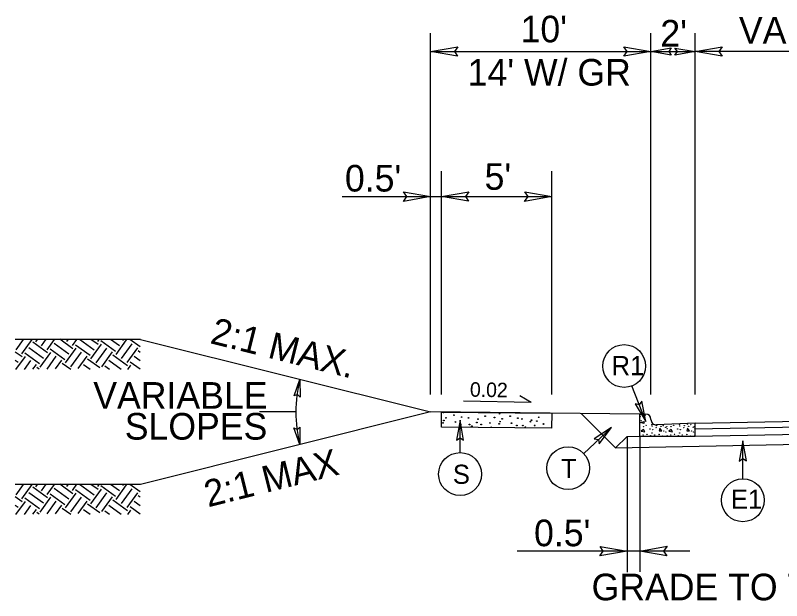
# Model space of a CAD drawing. Extents: x 3025871 to 3026431, y 707165 to 707825.
# Drawn here: x 3026298.56 to 3026333.34, y 707641.03 to 707667.61 of the extents above; entities that cross this region are included whole.
import ezdxf

# ---------------------------------------------------------------- set-up
doc = ezdxf.new("R2010")
doc.units = 0
for name, color, linetype in [('Prop Drainage Structure Junction Box with Manhole CELL', 7, 'Continuous'), ('Prop Drainage Structure Junction Box with Slab Lid TB 840 34 CELL', 7, 'Continuous'), ('Prop Drainage Structure Plot Symbol 50 Scale', 7, 'Continuous'), ('Prop Pavement Schedule Description CELL', 7, 'Continuous'), ('Sheet Plot Border Inside CELL', 7, 'Continuous'), ('Sheet Sticker Incomplete CELL', 7, 'Continuous'), ('Sheet Typical CELL', 7, 'Continuous'), ('Typical Arrow Superelevation CELL', 7, 'Continuous'), ('Typical Grade Point Symbol CELL', 7, 'Continuous'), ('Typical Text Centerline CELL', 7, 'Continuous'), ('Typical Text Grade Point CELL', 7, 'Continuous')]:
    doc.layers.add(name, color=color, linetype=linetype)

msp = doc.modelspace()

# ---------------------------------------------------------------- linework, layer by layer
at = {"layer": 'Prop Drainage Structure Junction Box with Manhole CELL'}
msp.add_line((3026325.802, 707647.974), (3026348.144, 707648.421), dxfattribs=at)
at = {"layer": 'Prop Drainage Structure Junction Box with Slab Lid TB 840 34 CELL'}
for p, q in [((3026317.406, 707650.399), (3026317.406, 707666.8)), ((3026327.406, 707650.399), (3026327.406, 707666.8)), ((3026329.412, 707650.658), (3026329.412, 707666.8)), ((3026317.406, 707665.967), (3026327.406, 707665.967)), ((3026327.406, 707665.967), (3026329.412, 707665.967)), ((3026350.162, 707665.967), (3026329.412, 707665.967)), ((3026329.412, 707650.399), (3026329.412, 707665.704)), ((3026317.906, 707650.399), (3026317.906, 707660.529)), ((3026322.906, 707650.399), (3026322.906, 707660.529)), ((3026313.391, 707659.381), (3026322.906, 707659.381)), ((3026311.291, 707649.599), (3026309.635, 707649.599)), ((3026326.319, 707648.49), (3026326.319, 707642.327)), ((3026326.904, 707648.502), (3026326.904, 707642.339)), ((3026329.174, 707643.282), (3026321.332, 707643.282))]:
    msp.add_line(p, q, dxfattribs=at)
msp.add_arc((3026317.406, 707649.599), 6.116, 165.9638, 194.0362, dxfattribs=at)
at = {"layer": 'Prop Drainage Structure Plot Symbol 50 Scale'}
for p, q in [((3026326.904, 707648.502), (3026326.904, 707649.506)), ((3026326.904, 707649.506), (3026327.165, 707649.506)), ((3026326.94, 707649.126), (3026327.095, 707649.171)), ((3026327.078, 707649.08), (3026326.94, 707649.126)), ((3026327.095, 707649.171), (3026327.078, 707649.08)), ((3026327.405, 707649.255), (3026327.405, 707649.265)), ((3026329.412, 707649.088), (3026327.656, 707649.015)), ((3026329.412, 707648.502), (3026329.412, 707649.088)), ((3026327.067, 707648.807), (3026326.963, 707648.731)), ((3026326.963, 707648.731), (3026327.129, 707648.692)), ((3026327.129, 707648.692), (3026327.067, 707648.807)), ((3026327.811, 707648.863), (3026327.777, 707648.749)), ((3026327.777, 707648.749), (3026327.897, 707648.743)), ((3026327.897, 707648.743), (3026327.811, 707648.863)), ((3026328.32, 707648.807), (3026328.217, 707648.731)), ((3026328.217, 707648.731), (3026328.383, 707648.692)), ((3026328.383, 707648.692), (3026328.32, 707648.807)), ((3026329.064, 707648.863), (3026329.03, 707648.749)), ((3026329.03, 707648.749), (3026329.151, 707648.743)), ((3026329.151, 707648.743), (3026329.064, 707648.863)), ((3026326.904, 707648.502), (3026329.412, 707648.502))]:
    msp.add_line(p, q, dxfattribs=at)
for centre in [(3026326.917, 707649.395), (3026327.135, 707649.43), (3026326.969, 707649.212), (3026327.187, 707648.989), (3026327.444, 707649.017), (3026327.668, 707648.983), (3026327.96, 707648.987), (3026328.44, 707648.989), (3026328.698, 707649.017), (3026328.921, 707648.983), (3026329.07, 707649.046), (3026329.214, 707649.029), (3026327.066, 707648.938), (3026327.364, 707648.823), (3026327.456, 707648.64), (3026327.461, 707648.967), (3026327.49, 707648.795), (3026327.639, 707648.881), (3026327.863, 707648.944), (3026327.988, 707648.743), (3026328.069, 707648.904), (3026328.085, 707648.697), (3026328.125, 707648.938), (3026328.142, 707648.841), (3026328.32, 707648.938), (3026328.618, 707648.823), (3026328.709, 707648.64), (3026328.715, 707648.967), (3026328.744, 707648.795), (3026328.893, 707648.881), (3026329.116, 707648.944), (3026329.242, 707648.743), (3026329.322, 707648.904), (3026329.339, 707648.697), (3026329.379, 707648.938), (3026329.396, 707648.841), (3026327.049, 707648.548), (3026327.221, 707648.589), (3026327.398, 707648.526), (3026327.57, 707648.554), (3026327.777, 707648.577), (3026327.937, 707648.508), (3026328.148, 707648.531), (3026328.303, 707648.548), (3026328.474, 707648.589), (3026328.652, 707648.526), (3026328.824, 707648.554), (3026329.03, 707648.577), (3026329.191, 707648.508), (3026329.402, 707648.531)]:
    msp.add_circle(centre, 0.00805, dxfattribs=at)
for centre, start, end in [((3026327.165, 707649.265), 0, 90), ((3026327.646, 707649.255), 180, 272.3845)]:
    msp.add_arc(centre, 0.24, start, end, dxfattribs=at)
at = {"layer": 'Prop Pavement Schedule Description CELL'}
for p, q in [((3026329.412, 707649.088), (3026362.162, 707649.743)), ((3026329.412, 707648.838), (3026348.148, 707649.212)), ((3026329.412, 707648.504), (3026348.146, 707648.879))]:
    msp.add_line(p, q, dxfattribs=at)
at = {"layer": 'Sheet Plot Border Inside CELL'}
msp.add_line((3026326.319, 707648.49), (3026326.904, 707648.502), dxfattribs=at)
at = {"layer": 'Sheet Sticker Incomplete CELL'}
for q in [(3026318.898, 707650.084), (3026321.45, 707650.338)]:
    msp.add_line((3026321.966, 707650.027), q, dxfattribs=at)
at = {"layer": 'Sheet Typical CELL'}
for p, q in [((3026326.904, 707649.506), (3026317.406, 707649.599)), ((3026317.893, 707648.917), (3026317.906, 707649.594)), ((3026317.906, 707649.594), (3026322.906, 707649.545)), ((3026322.906, 707649.545), (3026322.893, 707648.868)), ((3026325.802, 707647.974), (3026324.244, 707649.532)), ((3026322.893, 707648.868), (3026317.893, 707648.917)), ((3026326.319, 707648.49), (3026325.802, 707647.974))]:
    msp.add_line(p, q, dxfattribs=at)
for centre in [(3026317.989, 707649.572), (3026318.101, 707649.336), (3026318.465, 707649.458), (3026318.813, 707649.369), (3026319.127, 707649.328), (3026319.884, 707649.406), (3026320.302, 707649.351), (3026320.539, 707649.522), (3026321.015, 707649.408), (3026321.363, 707649.319), (3026322.31, 707649.359), (3026317.968, 707649.11), (3026318.005, 707649.213), (3026318.528, 707649.144), (3026318.771, 707649.036), (3026319.168, 707649.028), (3026319.505, 707649.121), (3026319.555, 707649.273), (3026319.702, 707649.029), (3026320.1, 707649.101), (3026320.518, 707649.06), (3026320.555, 707649.162), (3026320.651, 707649.286), (3026321.078, 707649.094), (3026321.321, 707648.986), (3026321.553, 707649.28), (3026321.594, 707648.981), (3026321.933, 707649.159), (3026321.981, 707649.225), (3026322.128, 707648.982), (3026322.225, 707649.188), (3026322.526, 707649.054), (3026319.28, 707648.956), (3026321.707, 707648.909)]:
    msp.add_circle(centre, 0.0164, dxfattribs=at)
msp.add_arc((3026320.154, 707648.892), 0.0164, 7.8354, 171.0404, dxfattribs=at)
at = {"layer": 'Typical Grade Point Symbol CELL'}
for p, q in [((3026327.167, 707649.173), (3026326.543, 707650.781)), ((3026318.742, 707647.753), (3026318.741, 707649.228)), ((3026324.355, 707647.709), (3026325.612, 707648.889)), ((3026331.579, 707646.562), (3026331.578, 707648.287))]:
    msp.add_line(p, q, dxfattribs=at)
for centre in [(3026326.192, 707651.687), (3026323.645, 707647.045), (3026318.742, 707646.781), (3026331.579, 707645.59)]:
    msp.add_circle(centre, 0.972, dxfattribs=at)
at = {"layer": 'Typical Text Centerline CELL'}
for points in [[(3026318.632, 707665.756), (3026317.406, 707665.967), (3026318.638, 707666.185), (3026318.482, 707665.967)], [(3026326.181, 707666.178), (3026327.406, 707665.967), (3026326.174, 707665.75), (3026326.331, 707665.967)], [(3026328.325, 707665.809), (3026327.406, 707665.967), (3026328.33, 707666.131), (3026328.212, 707665.967)], [(3026328.496, 707666.126), (3026329.414, 707665.967), (3026328.491, 707665.804), (3026328.608, 707665.967)], [(3026330.638, 707665.756), (3026329.412, 707665.967), (3026330.644, 707666.185), (3026330.488, 707665.967)], [(3026316.181, 707659.592), (3026317.406, 707659.381), (3026316.174, 707659.163), (3026316.331, 707659.381)], [(3026319.132, 707659.17), (3026317.906, 707659.381), (3026319.138, 707659.599), (3026318.982, 707659.381)], [(3026321.681, 707659.592), (3026322.906, 707659.381), (3026321.674, 707659.163), (3026321.831, 707659.381)], [(3026311.209, 707650.326), (3026311.474, 707651.082), (3026311.481, 707650.276), (3026311.359, 707650.398)], [(3026326.691, 707649.965), (3026327.167, 707649.173), (3026326.986, 707650.084), (3026326.878, 707649.918)], [(3026318.898, 707648.318), (3026318.741, 707649.227), (3026318.58, 707648.313), (3026318.741, 707648.429)], [(3026311.476, 707648.917), (3026311.474, 707648.116), (3026311.203, 707648.876), (3026311.358, 707648.8)], [(3026325.056, 707648.153), (3026325.612, 707648.889), (3026324.835, 707648.381), (3026325.03, 707648.343)], [(3026331.735, 707647.377), (3026331.578, 707648.287), (3026331.416, 707647.372), (3026331.578, 707647.488)], [(3026325.094, 707643.493), (3026326.319, 707643.282), (3026325.088, 707643.065), (3026325.244, 707643.282)], [(3026328.129, 707643.071), (3026326.904, 707643.282), (3026328.136, 707643.5), (3026327.979, 707643.282)]]:
    msp.add_lwpolyline(points, close=True, dxfattribs=at)
at = {"layer": 'Typical Text Grade Point CELL'}
for p, q in [((3026304.241, 707652.89), (3026298.557, 707652.89)), ((3026304.241, 707652.89), (3026298.557, 707652.89)), ((3026298.597, 707652.421), (3026298.935, 707652.89)), ((3026298.597, 707652.421), (3026298.935, 707652.89)), ((3026298.848, 707652.24), (3026299.315, 707652.89)), ((3026298.848, 707652.24), (3026299.315, 707652.89)), ((3026299.495, 707652.789), (3026299.568, 707652.89)), ((3026299.495, 707652.789), (3026299.568, 707652.89)), ((3026299.746, 707652.609), (3026299.957, 707652.902)), ((3026299.746, 707652.609), (3026299.957, 707652.902)), ((3026299.996, 707652.428), (3026300.328, 707652.89)), ((3026299.996, 707652.428), (3026300.328, 707652.89)), ((3026301.169, 707652.473), (3026300.574, 707652.901)), ((3026301.169, 707652.473), (3026300.574, 707652.901)), ((3026300.894, 707652.797), (3026300.968, 707652.899)), ((3026300.894, 707652.797), (3026300.968, 707652.899)), ((3026301.145, 707652.617), (3026301.348, 707652.898)), ((3026301.145, 707652.617), (3026301.348, 707652.898)), ((3026302.137, 707652.41), (3026301.469, 707652.891)), ((3026302.137, 707652.41), (3026301.469, 707652.891)), ((3026302.317, 707652.661), (3026301.99, 707652.896)), ((3026302.317, 707652.661), (3026301.99, 707652.896)), ((3026302.294, 707652.805), (3026302.359, 707652.895)), ((3026302.294, 707652.805), (3026302.359, 707652.895)), ((3026303.106, 707652.348), (3026302.437, 707652.828)), ((3026303.106, 707652.348), (3026302.437, 707652.828)), ((3026303.286, 707652.598), (3026302.875, 707652.894)), ((3026303.286, 707652.598), (3026302.875, 707652.894)), ((3026303.129, 707652.204), (3026303.61, 707652.873)), ((3026303.129, 707652.204), (3026303.61, 707652.873)), ((3026303.466, 707652.849), (3026303.406, 707652.892)), ((3026303.466, 707652.849), (3026303.406, 707652.892)), ((3026304.22, 707652.561), (3026303.76, 707652.891)), ((3026304.22, 707652.561), (3026303.76, 707652.891)), ((3026304.241, 707652.89), (3026317.406, 707649.599)), ((3026299.84, 707652.034), (3026299.171, 707652.515)), ((3026299.84, 707652.034), (3026299.171, 707652.515)), ((3026300.02, 707652.285), (3026299.352, 707652.765)), ((3026300.02, 707652.285), (3026299.352, 707652.765)), ((3026300.989, 707652.222), (3026300.32, 707652.703)), ((3026300.989, 707652.222), (3026300.32, 707652.703)), ((3026300.832, 707651.828), (3026301.312, 707652.496)), ((3026300.832, 707651.828), (3026301.312, 707652.496)), ((3026301.957, 707652.16), (3026301.289, 707652.64)), ((3026301.957, 707652.16), (3026301.289, 707652.64)), ((3026301.981, 707652.016), (3026302.461, 707652.685)), ((3026301.981, 707652.016), (3026302.461, 707652.685)), ((3026302.231, 707651.836), (3026302.712, 707652.504)), ((3026302.231, 707651.836), (3026302.712, 707652.504)), ((3026303.38, 707652.024), (3026303.86, 707652.692)), ((3026303.38, 707652.024), (3026303.86, 707652.692)), ((3026303.631, 707651.844), (3026304.111, 707652.512)), ((3026303.631, 707651.844), (3026304.111, 707652.512)), ((3026298.871, 707652.097), (3026298.557, 707652.323)), ((3026298.871, 707652.097), (3026298.557, 707652.323)), ((3026298.585, 707651.522), (3026299.015, 707652.12)), ((3026298.585, 707651.522), (3026299.015, 707652.12)), ((3026299.66, 707651.784), (3026298.991, 707652.264)), ((3026299.66, 707651.784), (3026298.991, 707652.264)), ((3026299.683, 707651.64), (3026300.164, 707652.308)), ((3026299.683, 707651.64), (3026300.164, 707652.308)), ((3026299.999, 707651.55), (3026300.414, 707652.128)), ((3026299.999, 707651.55), (3026300.414, 707652.128)), ((3026300.808, 707651.972), (3026300.14, 707652.452)), ((3026300.808, 707651.972), (3026300.14, 707652.452)), ((3026301.083, 707651.648), (3026301.563, 707652.316)), ((3026301.083, 707651.648), (3026301.563, 707652.316)), ((3026301.413, 707651.579), (3026301.814, 707652.136)), ((3026301.413, 707651.579), (3026301.814, 707652.136)), ((3026302.482, 707651.656), (3026302.962, 707652.324)), ((3026302.482, 707651.656), (3026302.962, 707652.324)), ((3026303.654, 707651.7), (3026302.986, 707652.181)), ((3026303.654, 707651.7), (3026302.986, 707652.181)), ((3026304.22, 707651.928), (3026303.954, 707652.118)), ((3026304.22, 707651.928), (3026303.954, 707652.118)), ((3026304.22, 707652.308), (3026304.134, 707652.369)), ((3026304.22, 707652.308), (3026304.134, 707652.369)), ((3026298.691, 707651.846), (3026298.557, 707651.943)), ((3026298.691, 707651.846), (3026298.557, 707651.943)), ((3026298.97, 707651.53), (3026299.265, 707651.94)), ((3026298.97, 707651.53), (3026299.265, 707651.94)), ((3026300.384, 707651.558), (3026300.665, 707651.948)), ((3026300.384, 707651.558), (3026300.665, 707651.948)), ((3026301.07, 707651.53), (3026300.688, 707651.805)), ((3026301.07, 707651.53), (3026300.688, 707651.805)), ((3026302.386, 707651.598), (3026301.837, 707651.993)), ((3026302.386, 707651.598), (3026301.837, 707651.993)), ((3026303.362, 707651.53), (3026302.806, 707651.93)), ((3026303.362, 707651.53), (3026302.806, 707651.93)), ((3026304.22, 707651.547), (3026303.774, 707651.867)), ((3026304.22, 707651.547), (3026303.774, 707651.867)), ((3026299.356, 707651.537), (3026299.516, 707651.76)), ((3026299.356, 707651.537), (3026299.516, 707651.76)), ((3026299.642, 707651.543), (3026299.54, 707651.616)), ((3026299.642, 707651.543), (3026299.54, 707651.616)), ((3026301.952, 707651.53), (3026301.657, 707651.742)), ((3026301.952, 707651.53), (3026301.657, 707651.742)), ((3026302.833, 707651.53), (3026302.626, 707651.679)), ((3026302.833, 707651.53), (3026302.626, 707651.679)), ((3026303.659, 707651.53), (3026303.798, 707651.724)), ((3026303.659, 707651.53), (3026303.798, 707651.724)), ((3026317.406, 707649.599), (3026304.241, 707646.308)), ((3026304.241, 707646.308), (3026298.557, 707646.308)), ((3026304.241, 707646.308), (3026298.557, 707646.308)), ((3026298.597, 707645.838), (3026298.935, 707646.308)), ((3026298.597, 707645.838), (3026298.935, 707646.308)), ((3026298.848, 707645.658), (3026299.315, 707646.308)), ((3026298.848, 707645.658), (3026299.315, 707646.308)), ((3026299.495, 707646.206), (3026299.568, 707646.308)), ((3026299.495, 707646.206), (3026299.568, 707646.308)), ((3026299.746, 707646.026), (3026299.957, 707646.32)), ((3026299.746, 707646.026), (3026299.957, 707646.32)), ((3026299.996, 707645.846), (3026300.328, 707646.308)), ((3026299.996, 707645.846), (3026300.328, 707646.308)), ((3026301.169, 707645.89), (3026300.574, 707646.318)), ((3026301.169, 707645.89), (3026300.574, 707646.318)), ((3026300.894, 707646.214), (3026300.968, 707646.317)), ((3026300.894, 707646.214), (3026300.968, 707646.317)), ((3026301.145, 707646.034), (3026301.348, 707646.316)), ((3026301.145, 707646.034), (3026301.348, 707646.316)), ((3026302.137, 707645.828), (3026301.469, 707646.308)), ((3026302.137, 707645.828), (3026301.469, 707646.308)), ((3026302.317, 707646.078), (3026301.99, 707646.314)), ((3026302.317, 707646.078), (3026301.99, 707646.314)), ((3026302.294, 707646.222), (3026302.359, 707646.313)), ((3026302.294, 707646.222), (3026302.359, 707646.313)), ((3026303.106, 707645.765), (3026302.437, 707646.246)), ((3026303.106, 707645.765), (3026302.437, 707646.246)), ((3026303.286, 707646.016), (3026302.875, 707646.311)), ((3026303.286, 707646.016), (3026302.875, 707646.311)), ((3026303.129, 707645.622), (3026303.61, 707646.29)), ((3026303.129, 707645.622), (3026303.61, 707646.29)), ((3026303.466, 707646.266), (3026303.406, 707646.31)), ((3026303.466, 707646.266), (3026303.406, 707646.31)), ((3026304.22, 707645.978), (3026303.76, 707646.309)), ((3026304.22, 707645.978), (3026303.76, 707646.309)), ((3026299.84, 707645.452), (3026299.171, 707645.932)), ((3026299.84, 707645.452), (3026299.171, 707645.932)), ((3026300.02, 707645.702), (3026299.352, 707646.183)), ((3026300.02, 707645.702), (3026299.352, 707646.183)), ((3026300.808, 707645.389), (3026300.14, 707645.869)), ((3026300.808, 707645.389), (3026300.14, 707645.869)), ((3026300.989, 707645.64), (3026300.32, 707646.12)), ((3026300.989, 707645.64), (3026300.32, 707646.12)), ((3026300.832, 707645.245), (3026301.312, 707645.914)), ((3026300.832, 707645.245), (3026301.312, 707645.914)), ((3026301.957, 707645.577), (3026301.289, 707646.057)), ((3026301.957, 707645.577), (3026301.289, 707646.057)), ((3026301.981, 707645.434), (3026302.461, 707646.102)), ((3026301.981, 707645.434), (3026302.461, 707646.102)), ((3026302.231, 707645.253), (3026302.712, 707645.922)), ((3026302.231, 707645.253), (3026302.712, 707645.922)), ((3026303.38, 707645.441), (3026303.86, 707646.11)), ((3026303.38, 707645.441), (3026303.86, 707646.11)), ((3026303.631, 707645.261), (3026304.111, 707645.93)), ((3026303.631, 707645.261), (3026304.111, 707645.93)), ((3026298.871, 707645.514), (3026298.557, 707645.74)), ((3026298.871, 707645.514), (3026298.557, 707645.74)), ((3026298.585, 707644.939), (3026299.015, 707645.538)), ((3026298.585, 707644.939), (3026299.015, 707645.538)), ((3026299.66, 707645.201), (3026298.991, 707645.681)), ((3026299.66, 707645.201), (3026298.991, 707645.681)), ((3026299.683, 707645.057), (3026300.164, 707645.726)), ((3026299.683, 707645.057), (3026300.164, 707645.726)), ((3026299.999, 707644.968), (3026300.414, 707645.546)), ((3026299.999, 707644.968), (3026300.414, 707645.546)), ((3026301.083, 707645.065), (3026301.563, 707645.734)), ((3026301.083, 707645.065), (3026301.563, 707645.734)), ((3026301.413, 707644.996), (3026301.814, 707645.554)), ((3026301.413, 707644.996), (3026301.814, 707645.554)), ((3026302.482, 707645.073), (3026302.962, 707645.742)), ((3026302.482, 707645.073), (3026302.962, 707645.742)), ((3026303.654, 707645.118), (3026302.986, 707645.598)), ((3026303.654, 707645.118), (3026302.986, 707645.598)), ((3026304.22, 707645.345), (3026303.954, 707645.536)), ((3026304.22, 707645.345), (3026303.954, 707645.536)), ((3026304.22, 707645.725), (3026304.134, 707645.786)), ((3026304.22, 707645.725), (3026304.134, 707645.786)), ((3026298.691, 707645.264), (3026298.557, 707645.36)), ((3026298.691, 707645.264), (3026298.557, 707645.36)), ((3026298.97, 707644.947), (3026299.265, 707645.358)), ((3026298.97, 707644.947), (3026299.265, 707645.358)), ((3026299.356, 707644.955), (3026299.516, 707645.177)), ((3026299.356, 707644.955), (3026299.516, 707645.177)), ((3026300.384, 707644.975), (3026300.665, 707645.366)), ((3026300.384, 707644.975), (3026300.665, 707645.366)), ((3026301.07, 707644.948), (3026300.688, 707645.222)), ((3026301.07, 707644.948), (3026300.688, 707645.222)), ((3026301.952, 707644.948), (3026301.657, 707645.159)), ((3026301.952, 707644.948), (3026301.657, 707645.159)), ((3026302.386, 707645.016), (3026301.837, 707645.41)), ((3026302.386, 707645.016), (3026301.837, 707645.41)), ((3026303.362, 707644.948), (3026302.806, 707645.347)), ((3026303.362, 707644.948), (3026302.806, 707645.347)), ((3026304.22, 707644.965), (3026303.774, 707645.285)), ((3026304.22, 707644.965), (3026303.774, 707645.285)), ((3026299.642, 707644.96), (3026299.54, 707645.034)), ((3026299.642, 707644.96), (3026299.54, 707645.034)), ((3026302.833, 707644.948), (3026302.626, 707645.097)), ((3026302.833, 707644.948), (3026302.626, 707645.097)), ((3026303.659, 707644.948), (3026303.798, 707645.141)), ((3026303.659, 707644.948), (3026303.798, 707645.141))]:
    msp.add_line(p, q, dxfattribs=at)

# ---------------------------------------------------------------- texts
at = {"layer": 'Prop Drainage Structure Junction Box with Slab Lid TB 840 34 CELL'}
for s, height, p in [("10'", 1.2089, (3026321.488, 707666.385)), ("2'", 1.2089, (3026327.833, 707666.193)), ("VAR. 0'-12'", 1.20892, (3026331.398, 707666.329)), ("14' W/ GR", 1.2089, (3026319.088, 707664.42)), ("0.5'", 1.2089, (3026313.517, 707659.61)), ("5'", 1.2089, (3026319.855, 707659.689)), ("0.5'", 1.2089, (3026322.1, 707643.503)), ('GRADE TO THIS LINE', 1.20892, (3026324.711, 707641.048))]:
    msp.add_text(s, height=height, dxfattribs=at).set_placement(p)
at = {"layer": 'Sheet Sticker Incomplete CELL'}
msp.add_text('0.02', height=0.6583, rotation=358.9408, dxfattribs=at).set_placement((3026319.186, 707650.296))
at = {"layer": 'Typical Arrow Superelevation CELL'}
for s, p in [('R1', (3026325.617, 707651.271)), ('T', (3026323.324, 707646.597))]:
    msp.add_text(s, height=0.87, rotation=360, dxfattribs=at).set_placement(p)
for s, p in [('S', (3026318.413, 707646.336)), ('E1', (3026331.033, 707645.207))]:
    msp.add_text(s, height=0.87, dxfattribs=at).set_placement(p)
at = {"layer": 'Typical Text Grade Point CELL'}
for s, rotation, p in [('2:1 MAX.', 345.9638, (3026307.352, 707652.731)), ('2:1 MAX', 14.0362, (3026307.306, 707645.267))]:
    msp.add_text(s, height=1.2089, rotation=rotation, dxfattribs=at).set_placement(p)
for s, p in [('VARIABLE', (3026302.095, 707649.747)), ('SLOPES', (3026303.524, 707648.345))]:
    msp.add_text(s, height=1.2089, dxfattribs=at).set_placement(p)

doc.saveas('drawing.dxf')
